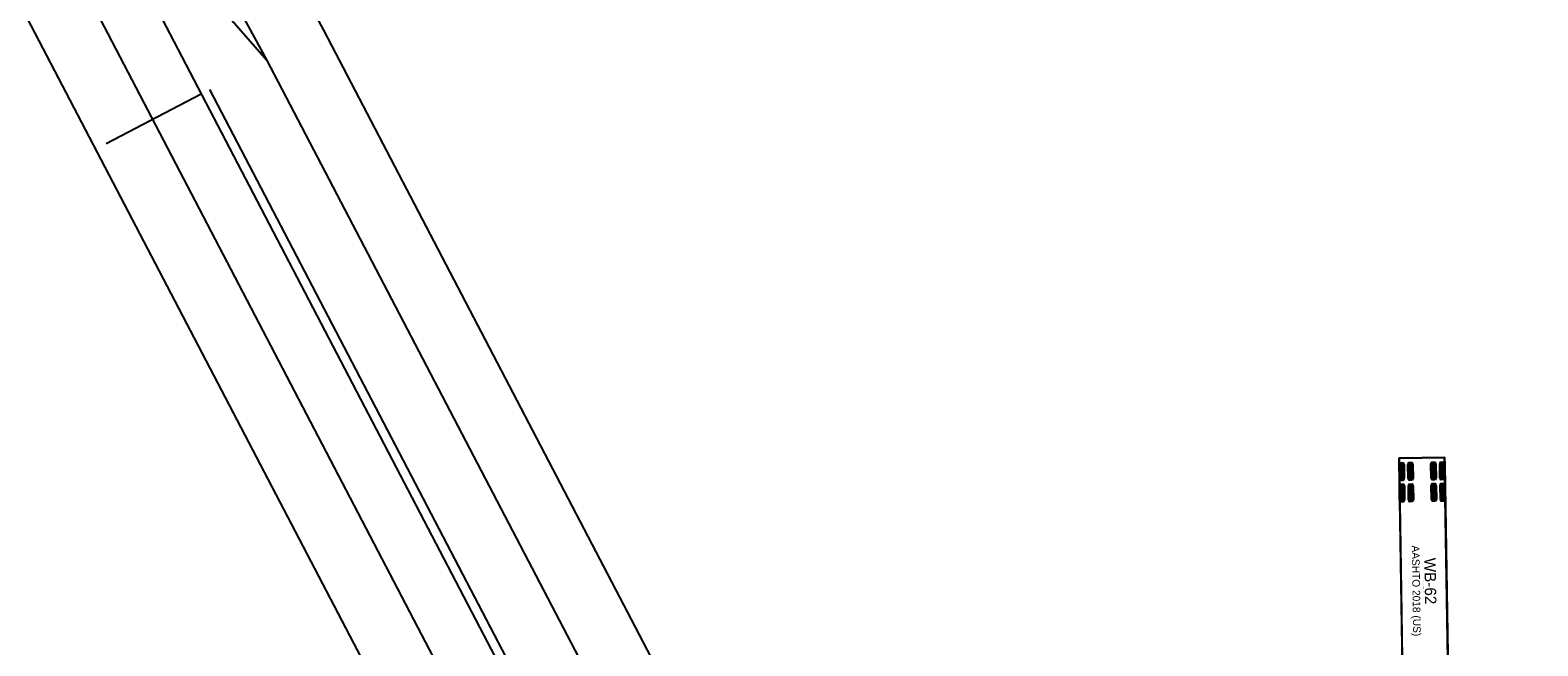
# Model space of a CAD drawing. Extents: x 2297881 to 2300600, y 559917 to 564426.
# Drawn here: x 2298788.6 to 2299069.8, y 562848.3 to 562963.3 of the extents above; entities that cross this region are included whole.
import ezdxf

# ---------------------------------------------------------------- set-up
doc = ezdxf.new("R2010")
doc.units = 0
for name, color, linetype in [('GE_X_Alignment', 7, 'Continuous'), ('PM_P_Channelizing_Line', 7, 'Continuous'), ('PM_P_CL_Pass_Proh_Lt', 7, 'Continuous'), ('PM_P_Dotted_Line', 7, 'Continuous'), ('PM_P_Lane_Line', 7, 'Continuous'), ('SC_Scratch1', 7, 'Continuous'), ('SV_X_Control_Cells_Found', 7, 'Continuous')]:
    doc.layers.add(name, color=color, linetype=linetype)

msp = doc.modelspace()

# ---------------------------------------------------------------- linework, layer by layer
at = {"layer": 'GE_X_Alignment'}
msp.add_line((2298386.28, 563783.36), (2299396.64, 561847.4), dxfattribs=at)
at = {"layer": 'PM_P_Channelizing_Line'}
for p, q in [((2299052.44, 562883.5), (2299043.94, 562883.36)), ((2299043.94, 562883.36), (2299044.72, 562835.37)), ((2299053.22, 562835.5), (2299052.44, 562883.5)), ((2299044.24, 562879.21), (2299044.18, 562882.51)), ((2299044.47, 562879.22), (2299044.41, 562882.52)), ((2299044.69, 562879.22), (2299044.64, 562882.52)), ((2299045.89, 562879.24), (2299045.83, 562882.54)), ((2299046.12, 562879.25), (2299046.06, 562882.54)), ((2299046.34, 562879.25), (2299046.29, 562882.55)), ((2299050.17, 562879.31), (2299050.12, 562882.61)), ((2299050.4, 562879.31), (2299050.34, 562882.61)), ((2299050.63, 562879.32), (2299050.57, 562882.62)), ((2299051.82, 562879.34), (2299051.76, 562882.64)), ((2299052.05, 562879.34), (2299051.99, 562882.64)), ((2299052.28, 562879.35), (2299052.22, 562882.65)), ((2299044.3, 562875.22), (2299044.25, 562878.51)), ((2299044.53, 562875.22), (2299044.48, 562878.52)), ((2299044.76, 562875.22), (2299044.71, 562878.52)), ((2299045.95, 562875.24), (2299045.9, 562878.54)), ((2299046.18, 562875.25), (2299046.13, 562878.55)), ((2299046.41, 562875.25), (2299046.36, 562878.55)), ((2299050.23, 562875.31), (2299050.18, 562878.61)), ((2299050.46, 562875.32), (2299050.41, 562878.62)), ((2299050.69, 562875.32), (2299050.64, 562878.62)), ((2299051.88, 562875.34), (2299051.83, 562878.64)), ((2299052.11, 562875.34), (2299052.06, 562878.64)), ((2299052.34, 562875.35), (2299052.29, 562878.65))]:
    msp.add_line(p, q, dxfattribs=at)
for points in [[(2299045.2, 562805.18), (2299043.94, 562883.36), (2299052.44, 562883.5), (2299052.46, 562882.1)], [(2299052.46, 562882.1), (2299053.68, 562807.36)]]:
    msp.add_lwpolyline(points, dxfattribs=at)
for points in [[(2299044.75, 562879.22), (2299044.18, 562879.21), (2299044, 562879.67), (2299043.96, 562882.05), (2299044.13, 562882.51), (2299044.7, 562882.52), (2299044.88, 562882.06), (2299044.92, 562879.69)], [(2299046.4, 562879.25), (2299045.83, 562879.24), (2299045.65, 562879.7), (2299045.61, 562882.08), (2299045.78, 562882.54), (2299046.35, 562882.55), (2299046.53, 562882.09), (2299046.57, 562879.71)], [(2299050.68, 562879.32), (2299050.11, 562879.31), (2299049.93, 562879.77), (2299049.89, 562882.15), (2299050.06, 562882.61), (2299050.63, 562882.62), (2299050.81, 562882.16), (2299050.85, 562879.78)], [(2299052.33, 562879.35), (2299051.76, 562879.34), (2299051.58, 562879.8), (2299051.54, 562882.17), (2299051.71, 562882.64), (2299052.28, 562882.65), (2299052.46, 562882.19), (2299052.5, 562879.81)], [(2299044.82, 562875.22), (2299044.24, 562875.21), (2299044.06, 562875.67), (2299044.03, 562878.05), (2299044.19, 562878.51), (2299044.76, 562878.52), (2299044.94, 562878.06), (2299044.98, 562875.69)], [(2299046.47, 562875.25), (2299045.89, 562875.24), (2299045.71, 562875.7), (2299045.68, 562878.08), (2299045.84, 562878.54), (2299046.41, 562878.55), (2299046.59, 562878.09), (2299046.63, 562875.72)], [(2299050.75, 562875.32), (2299050.18, 562875.31), (2299050, 562875.77), (2299049.96, 562878.15), (2299050.12, 562878.61), (2299050.7, 562878.62), (2299050.87, 562878.16), (2299050.91, 562875.78)], [(2299052.4, 562875.35), (2299051.83, 562875.34), (2299051.65, 562875.8), (2299051.61, 562878.17), (2299051.77, 562878.64), (2299052.34, 562878.65), (2299052.52, 562878.19), (2299052.56, 562875.81)]]:
    msp.add_lwpolyline(points, close=True, dxfattribs=at)
at = {"layer": 'PM_P_CL_Pass_Proh_Lt'}
for p, q in [((2298488.92, 563590.46), (2298832.69, 562957.71)), ((2298798.91, 562996.48), (2298832.69, 562957.71)), ((2298832.69, 562957.71), (2298969.18, 562696.18))]:
    msp.add_line(p, q, dxfattribs=at)
at = {"layer": 'PM_P_Dotted_Line'}
msp.add_line((2298822.05, 562952.16), (2298958.54, 562690.63), dxfattribs=at)
at = {"layer": 'PM_P_Lane_Line'}
for p, q in [((2298499.56, 563596.01), (2298843.32, 562963.26)), ((2298467.65, 563579.35), (2299376.95, 561837.04)), ((2298843.32, 562963.26), (2299419.43, 561859.39))]:
    msp.add_line(p, q, dxfattribs=at)
at = {"layer": 'SC_Scratch1'}
msp.add_line((2298802.77, 562942.1), (2298820.5, 562951.35), dxfattribs=at)
at = {"layer": 'SV_X_Control_Cells_Found'}
msp.add_line((2298478.28, 563584.91), (2298947.9, 562685.08), dxfattribs=at)

# ---------------------------------------------------------------- texts
at = {"layer": 'PM_P_Channelizing_Line'}
for s, height, p in [('AASHTO 2018 (US)', 1.4167, (2299046.32, 562867.06)), ('WB-62', 2.125, (2299048.66, 562864.75)), ('(c) 2021 Transoft Solutions, Inc. All rights reserved.', 0.085, (2299048.51, 562861.16))]:
    msp.add_text(s, height=height, rotation=270.9306, dxfattribs=at).set_placement(p)

doc.saveas('drawing.dxf')
